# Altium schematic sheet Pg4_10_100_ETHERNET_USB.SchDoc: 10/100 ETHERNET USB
size 431 x 279 mm; Date: Not shown in title block; ApprovedBy: Not shown in title block; CheckedBy: Not shown in title block; Author: Not shown in title block; CompanyName: Not shown in title block; Engineer: Not shown in title block; Organization: Not shown in title block; Address1: Not shown in title block; Address2: Not shown in title block; Address3: Not shown in title block; Address4: Not shown in title block; DocumentNumber: 4; Revision: Use project parameter SCH_Rev; SheetNumber: 4; SheetTotal: 9; PageSetup: Record=PageOptions|CenterHorizontal=True|CenterVertical=True|PrintScale=1.00|XCorrection=1.00|YCorrection=1.00|PrintKind=0|BorderSize=5000000|LeftOffset=0|BottomOffset=0|Orientation=2|PaperLength=1000|PaperWidth=1000|Scale=100|PaperSource=15|PrintQuality=600|MediaType=1|DitherType=10|PaperKind=Letter|PrintScaleMode=1
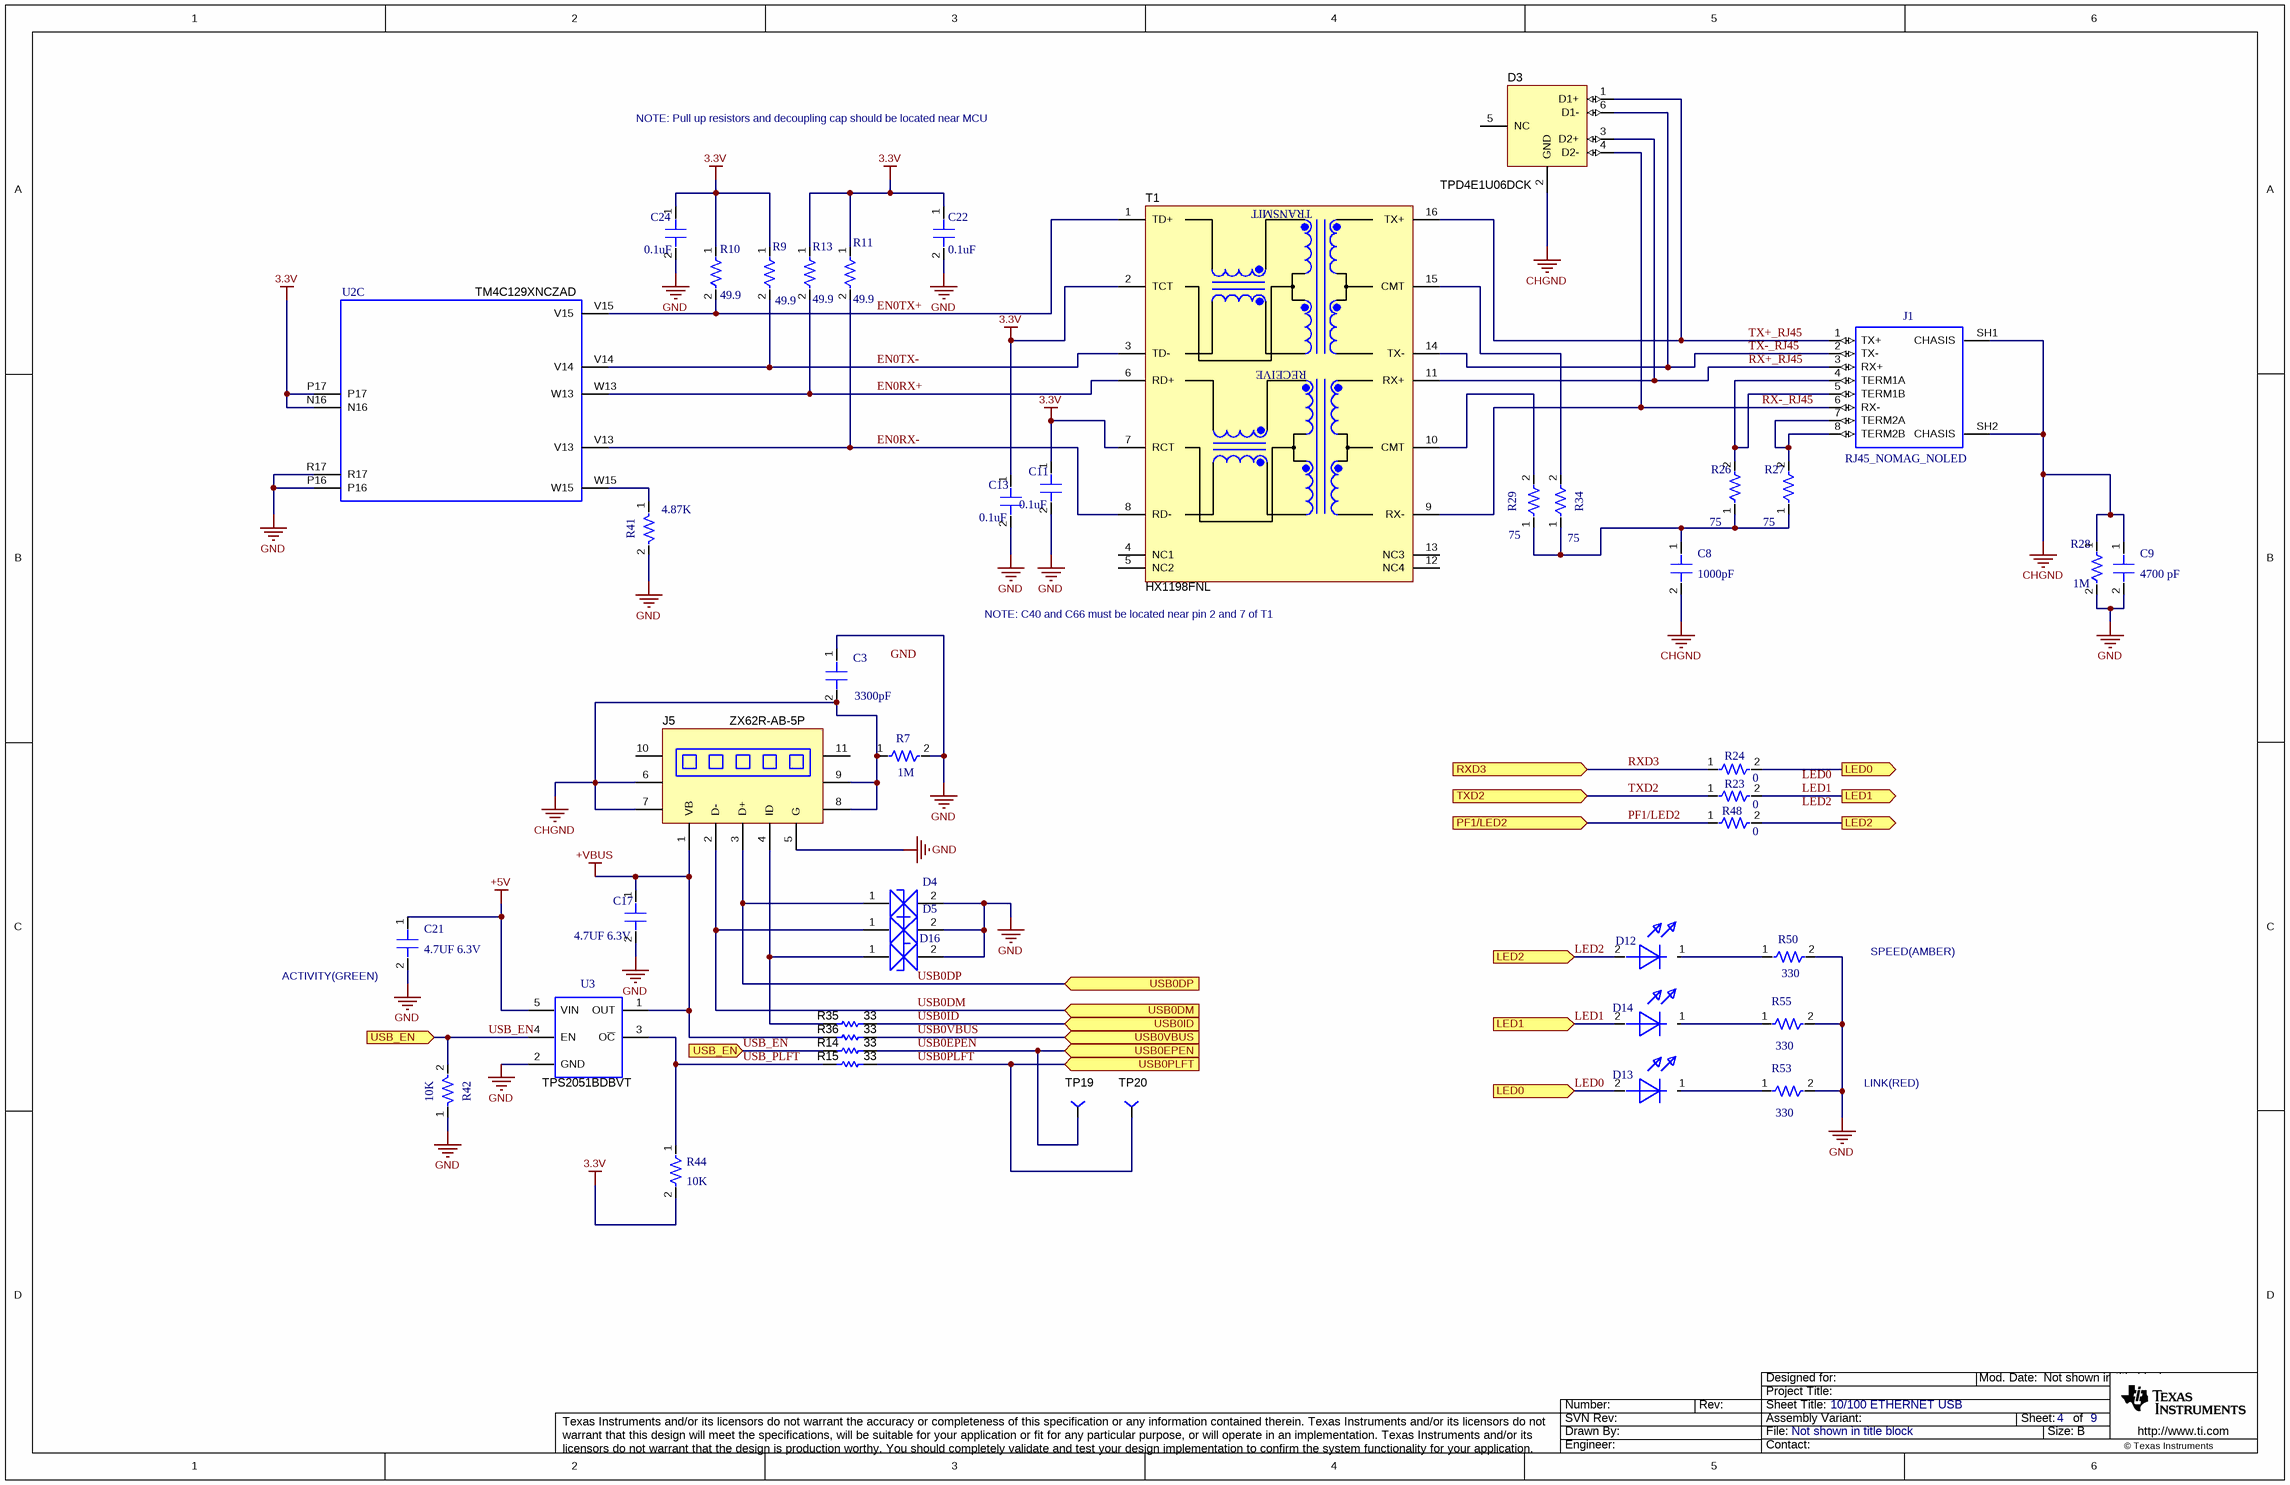
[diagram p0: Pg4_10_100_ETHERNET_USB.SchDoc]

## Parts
C3  value 3300pF  [0603]  (hidden comment: CAPC0603)
C8  value 1000pF  [1210]  (hidden comment: CAPC1210)
C9  value 4700 pF  [1812]  (hidden comment: CAPC0603)
C11  value 0.1uF  [0603]  (hidden comment: CAPC0603)
C13  value 0.1uF  [0603]  (hidden comment: CAPC0603)
C17  value 4.7UF 6.3V  [0805]  (hidden comment: CAPC0805)
C21  value 4.7UF 6.3V  [0805]  (hidden comment: CAPC0805)
C22  value 0.1uF  [0603]  (hidden comment: CAPC0603)
C24  value 0.1uF  [0603]  (hidden comment: CAPC0603)
D3  TPD4E1U06DCK  [DCK0006A_N]
D4  B72590D0050H160  [RESC0402N]  (value not drawn)
D5  B72590D0050H160  [RESC0402N]  (value not drawn)
D12  LED-0805  [DIOC0805N]  (value not drawn)
D13  LED-0805  [DIOC0805N]  (value not drawn)
D14  LED-0805  [DIOC0805N]  (value not drawn)
D16  B72590D0050H160  [RESC0402N]  (value not drawn)
J1  RJ45_NOMAG_NOLED  [TE_6116526-1]
J5  ZX62R-AB-5P  [CON-USB-MICRO-REV]
R7  value 1M  [0603]  (hidden comment: RESC0603)
R9  value 49.9  [0603]  (hidden comment: RESC0603)
R10  value 49.9  [0603]  (hidden comment: RESC0603)
R11  value 49.9  [0603]  (hidden comment: RESC0603)
R13  value 49.9  [0603]  (hidden comment: RESC0603)
R14  value 33  [0402]  (hidden comment: CRCW040233R0JNED)
R15  value 33  [0402]  (hidden comment: CRCW040233R0JNED)
R23  value 0  [0402]  (hidden comment: RESC0402)
R24  value 0  [0402]  (hidden comment: RESC0402)
R26  value 75  [0603]  (hidden comment: RESC0603)
R27  value 75  [0603]  (hidden comment: RESC0603)
R28  value 1M  [1206]  (hidden comment: RESC1206)
R29  value 75  [0603]  (hidden comment: RESC0603)
R34  value 75  [0603]  (hidden comment: RESC0603)
R35  value 33  [0402]  (hidden comment: CRCW040233R0JNED)
R36  value 33  [0402]  (hidden comment: CRCW040233R0JNED)
R41  value 4.87K  [0603]  (hidden comment: RESC0603)
R42  value 10K  [0603]  (hidden comment: RESC0603)
R44  value 10K  [0402]  (hidden comment: RESC0402)
R48  value 0  [0402]  (hidden comment: RESC0402)
R50  value 330  [0603]  (hidden comment: RESC0603)
R53  value 330  [0603]  (hidden comment: RESC0603)
R55  value 330  [0603]  (hidden comment: RESC0603)
T1  HX1198FNL  [XFMR_ HX1198FNL]
TP19  TP1_PD40_D0.5_S50  [TP1_PD40_D0.5_S50]  (value not drawn)
TP20  TP1_PD40_D0.5_S50  [TP1_PD40_D0.5_S50]  (value not drawn)
U2  Part Number: TM4C129XNCZAD  [BGA212C50P19X19_1000X1000X100]  (hidden comment: TM4C129X)  (part C of 3)
U3  Part Number: TPS2051BDBVT  [DBV5]  (hidden comment: TPS2051B)

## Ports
LED0, LED1, LED2, PF1/LED2, RXD3, TXD2, USB0DM, USB0DP, USB0EPEN, USB0ID, USB0PLFT, USB0VBUS, USB_EN

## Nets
3.3V: C11.1 C13.1 C22.1 C24.1 R9.1 R10.1 R11.1 R13.1 R44.2 T1.2(TCT) T1.7(RCT) U2.N16 U2.P17
+5V: C21.1 U3.5(VIN)
+VBUS: C17.1 J5.1(VB) R36.1 U3.1(OUT)
CHGND: C3.2 C8.2 C9.1 D3.2(GND) J1.SH1(CHASIS) J1.SH2(CHASIS) J5.6 J5.7 J5.8 J5.9 R7.1 R28.1
GND: C3.1 C9.2 C11.2 C13.2 C17.2 C21.2 C22.2 C24.2 D4.2 D5.2 D16.2 J5.5(G) R7.2 R28.2 R41.2 R42.1 R50.2 R53.2 R55.2 U2.P16 U2.R17 U3.2(GND)
EN0RX+: R13.2 T1.6(RD+) U2.W13
EN0RX-: R11.2 T1.8(RD-) U2.V13
EN0TX+: R10.2 T1.1(TD+) U2.V15
EN0TX-: R9.2 T1.3(TD-) U2.V14
LED0: D13.2 R24.2 ; port LED0
LED1: D14.2 R23.2 ; port LED1
LED2: D12.2 R48.2 ; port LED2
PF1/LED2: R48.1 ; port PF1/LED2
RX+_RJ45: D3.3(D2+) J1.3(RX+) T1.11(RX+)
RX-_RJ45: D3.4(D2-) J1.6(RX-) T1.9(RX-)
RXD3: R24.1 ; port RXD3
TX+_RJ45: D3.1(D1+) J1.1(TX+) T1.16(TX+)
TX-_RJ45: D3.6(D1-) J1.2(TX-) T1.14(TX-)
TXD2: R23.1 ; port TXD2
USB0DM: D5.1 J5.2(D-) ; port USB0DM
USB0DP: D4.1 J5.3(D+) ; port USB0DP
USB0EPEN: R14.2 TP19.1 ; port USB0EPEN
USB0ID: R35.2 ; port USB0ID
USB0PLFT: R15.2 TP20.1 ; port USB0PLFT
USB0VBUS: R36.2 ; port USB0VBUS
USB_EN: R14.1 R42.2 U3.4(EN) ; port USB_EN
USB_PLFT: R15.1 R44.1 U3.3(O~{C})
NetC8_1: C8.1 R26.1 R27.1 R29.1 R34.1
NetD12_1: D12.1 R50.1
NetD13_1: D13.1 R53.1
NetD14_1: D14.1 R55.1
NetD16_1: D16.1 J5.4(ID) R35.1
NetJ1_4: J1.4(TERM1A) J1.5(TERM1B) R26.2
NetJ1_7: J1.7(TERM2A) J1.8(TERM2B) R27.2
NetR29_2: R29.2 T1.10(CMT)
NetR34_2: R34.2 T1.15(CMT)
NetR41_1: R41.1 U2.W15

Not connected (* = marked no-connect by the designer): D3 5(NC); J5 10 11; T1 4(NC1) 5(NC2) 12(NC4) 13(NC3)

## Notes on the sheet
- NOTE: Pull up resistors and decoupling cap should be located near MCU
- (near T1) NOTE: C40 and C66 must be located near pin 2 and 7 of T1
- SPEED(AMBER)
- (near C21) ACTIVITY(GREEN)
- LINK(RED)
- Labels drawn without touching a wire or pin: $$$22985, GND, LED0, LED2

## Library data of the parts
C3 = CAPC0603: Capacitor, 3300pF, 50V, 10%, X7R, 0603; Part Number: C1608X7R1H332K; Sim.Analog.Order: Model$; PCB DECAL: CAPC0603N; GNUM: G10-C0603-C332-ABA
C8 = CAPC1210: CAP CER 1000PF 2KV 20% X7R 1210; Part Number: C1210C102MGRACTU; GNUM: G10-C1210-C102-ZCA
C9 = CAPC0603: Capacitor, 4700pF, 2kV, 10%, X7R, 1812; Part Number: 1812GC472KAT1A; GNUM: G10-C1812-C472-ZBA; PCB DECAL: 1812MIL
C11 C13 C22 C24 = CAPC0603: Capacitor, 0.1uF 50V, 20% 0603 X7R; Part Number: C1608X7R1H104M; GNUM: G10-C0603-C104-ACA; PCB DECAL: CAPC0603L
C17 C21 = CAPC0805: Capacitor, 4.7uF, 6.3V, 10% 0805, X5R; Part Number: JMK212BJ475KG-T; GNUM: G10-C0805-C475-DBB; Geometry.Height: 1.1mm; PCBL.Component: CHP;CAPC;1800;2200;250;750;1050;1450;1100; PCBL.Process: F;N;50;50;200;100;200;250;350;-50;0
D3 = TPD4E1U06DCK: Quad Channel High Speed ESD Protection Device, DCK0006A; Alternate Manufacturer: None; Manufacturer: Texas Instruments; SymbolCreator: a0411947; CompType: IC; U/M: EA
D4 D5 D16 = B72590D0050H160: Diode, 5.6V ESD Suppressor 0402; GNUM: G14-D0402-5V6-DAA
D12 = LED-0805: LED AMBER CLEAR 0805 SMD; Manufacturer #1: LITE-ON; Part Number: LTST-C170AKT; GNUM: G14-D0805-AMB0-AAA; Description: SMT LED IN 0805 PACK
D13 = LED-0805: LED, Red 630nm, Clear 0805 SMD; Manufacturer #1: LITE-ON; Part Number: LTST-C171EKT; Description: SMT LED IN 0805 PACK; GNUM: G14-D0805-RD00-AAA
D14 = LED-0805: LED, Green 565nm, Clear 0805 SMD; Manufacturer #1: LITE-ON; Part Number: LTST-C171GKT; Description: SMT LED IN 0805 PACK; GNUM: G14-D0805-GR00-AAA
J1 = RJ45_NOMAG_NOLED: Connector, RJ45 NO MAG, shielded THRU HOLE; Part Number: 6116526-1; PCB DECAL: 406541; GNUM: G20-8RJ45-ENET-AAA
J5 = ZX62R-AB-5P: Connector, USB micro AB Receptacle Reversed SMD; Manufacturer: HIROSE ELECTRIC CO. LTD.; SymbolCreator: x0199378
R7 = RESC0603: Resistor, 1M OHM 1/10W 5% 0603 SMD; Manufacturer #1: Generic; Part Number: ERJ-3GEYJ105V; Description: Resistor,Chip;1.60mm L X 0.83mm W X 0.60mm H; Geometry.Height: 0.6mm; PCBL.Component: CHP;RESC;1500;1700;150;400;700;950;600; PCBL.Process: F;N;50;50;200;100;200;250;350;-50;0; PCB DECAL: RESC0603N; GNUM: G11-R0603-R105-AAA
R9-R11 R13 = RESC0603: Resistor, 49.9 OHM 1/10W 1% 0603 Thick; Manufacturer #1: Generic; Part Number: ERJ-3EKF49R9V; Description: Resistor,Chip;1.60mm L X 0.83mm W X 0.60mm H; Geometry.Height: 0.6mm; PCBL.Component: CHP;RESC;1500;1700;150;400;700;950;600; PCBL.Process: F;N;50;50;200;100;200;250;350;-50;0; Tolerance: 5%; PCB DECAL: RESC0603N; GNUM: G11-R0603-49R9-ABA
R14 R15 R35 R36 = CRCW040233R0JNED: RES, 33 ohm, 5%, 0.063W, 0402; Manufacturer: Vishay-Dale; CompType: Resistor; Value_Code: 33R0; Tolerance_%: 5; Power_W: 0.063; VDC_V: 50; TempCo: 200 ppm/C; EIA_Code: E24; U/M: EA
R23 R24 R48 = RESC0402: Resistor, 0 ohm, 1/10W, 5%, 0402; Manufacturer #1: Generic; Part Number: ERJ-2GE0R00X; Description: Resistor,Chip;1.00mm L X 0.5mm W X 0.35mm H; Geometry.Height: 0.35mm; PCBL.Component: CHP;RESC;1500;1700;150;400;700;950;600; PCBL.Process: F;N;50;50;200;100;200;250;350;-50;0; PCB DECAL: RESC0402N; GNUM: G11-R0402-0000-AAA
R26 R27 R29 R34 = RESC0603: Resistor, 75 Ohm, 1/10W, 1%, SMD, Thick; Manufacturer #1: Generic; Part Number: ERJ-3EKF75R0V; PCB DECAL: RESC0603N; GNUM: G11-R0603-R750-ABA; Description: Resistor,Chip;1.60mm L X 0.83mm W X 0.60mm H; Geometry.Height: 0.6mm; PCBL.Component: CHP;RESC;1500;1700;150;400;700;950;600; PCBL.Process: F;N;50;50;200;100;200;250;350;-50;0
R28 = RESC1206: RES 1M OHM 5% 1206 TF; Manufacturer #1: IPC SM-782; Part Number: ERJ-8GEYJ105V; Description: SURFACE MOUNT RESISTOR OR CAPACITOR 0.062 X 0.126 INCHES; GNUM: G11-R1206-R105-CAA
R41 = RESC0603: Resistor, 4.87K Ohm, 1/10W, 1%, SMD, Thick; Manufacturer #1: Generic; Part Number: ERJ-3EKF4871V; Description: Resistor,Chip;1.60mm L X 0.83mm W X 0.60mm H; Geometry.Height: 0.6mm; PCBL.Component: CHP;RESC;1500;1700;150;400;700;950;600; PCBL.Process: F;N;50;50;200;100;200;250;350;-50;0; PCB DECAL: RESC0603N; GNUM: G11-R0603-4871-ABA
R42 = RESC0603: Resistor, 10K OHM 1/10W 5% 0603 SMD; Manufacturer #1: Generic; Part Number: ERJ-3GEYJ103V; PCB DECAL: RESC0603N; GNUM: G11-R0603-R103-AAA; Description: Resistor,Chip;1.60mm L X 0.83mm W X 0.60mm H; Geometry.Height: 0.6mm; PCBL.Component: CHP;RESC;1500;1700;150;400;700;950;600; PCBL.Process: F;N;50;50;200;100;200;250;350;-50;0
R44 = RESC0402: Resistor, 10k ohm, 1/10W, 5%, 0402 Thick Film; Manufacturer #1: Generic; Part Number: RC0402FR-0710KL; Description: Resistor,Chip;1.00mm L X 0.5mm W X 0.35mm H; Geometry.Height: 0.35mm; PCBL.Component: CHP;RESC;1500;1700;150;400;700;950;600; PCBL.Process: F;N;50;50;200;100;200;250;350;-50;0; PCB DECAL: RESC0402N; GNUM: G11-R0402-1002-AAA
R50 = RESC0603: Resistor, 330 OHM 1/10W 5% 0603 SMD; Manufacturer #1: Generic; Part Number: ERJ-3GEYJ331V; PCB DECAL: RESC0603N; GNUM: G11-R0603-R331-AAA; Description: Resistor,Chip;1.60mm L X 0.83mm W X 0.60mm H; Geometry.Height: 0.6mm; PCBL.Component: CHP;RESC;1500;1700;150;400;700;950;600; PCBL.Process: F;N;50;50;200;100;200;250;350;-50;0
R53 R55 = RESC0603: Resistor, 330 OHM 1/10W 5% 0603 SMD; Manufacturer #1: Generic; Part Number: ERJ-3GEYJ331V; Description: Resistor,Chip;1.60mm L X 0.83mm W X 0.60mm H; Geometry.Height: 0.6mm; PCBL.Component: CHP;RESC;1500;1700;150;400;700;950;600; PCBL.Process: F;N;50;50;200;100;200;250;350;-50;0; PCB DECAL: RESC0603N; GNUM: G11-R0603-R331-AAA
T1 = HX1198FNL: TRANSFORMER, MDL, XFMR SGL ETHR LAN, SOIC-16; Manufacturer: PULSE ELECTRONICS; SymbolCreator: x0199378
TP19 TP20 = TP-040_RND: Test Point 40mil pad 20mil drill; Manufacturer: STD; Description: Test Point, O.040 Hole; Value: STD
U2 = TM4C129X: Stellaris MCU TM4C129XNCZAD 212 BGA, super; GNUM: G50-BG212-C129-ALI; PCB DECAL: BGA19X19-05MM-T1; Geometry.Height: 50.00mil
U3 = TPS2051B: Load Switch, 5.5V, SOT23-5, TPS2051BDBV; GNUM: G41-SOT23-2051-AAA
